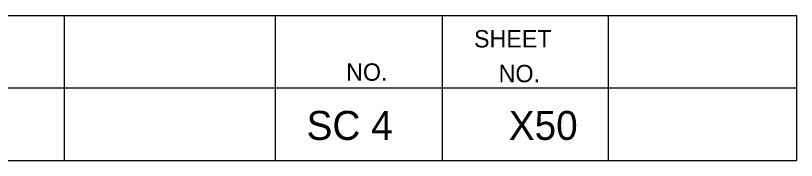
# Model space of a CAD drawing. Extents: x 1000 to 1162, y 999 to 8520.
# Drawn here: x 1148.08 to 1161.56, y 6735.05 to 6737.55 of the extents above; entities that cross this region are included whole.
import ezdxf

# ---------------------------------------------------------------- set-up
doc = ezdxf.new("R2010")
doc.units = 0
doc.layers.add('Level 20', color=7, linetype='Continuous')
doc.layers.add('Level 3', color=7, linetype='Continuous')

msp = doc.modelspace()

# ---------------------------------------------------------------- linework, layer by layer
at = {"layer": 'Level 3'}
for p, q in [((1133.055, 6737.546), (1161.555, 6737.546)), ((1133.055, 6737.546), (1161.555, 6737.546)), ((1133.055, 6737.546), (1161.555, 6737.546)), ((1133.055, 6737.546), (1161.555, 6737.546)), ((1133.055, 6737.546), (1161.555, 6737.546)), ((1133.055, 6737.546), (1161.555, 6737.546)), ((1133.055, 6737.546), (1161.555, 6737.546)), ((1133.055, 6737.546), (1161.555, 6737.546)), ((1133.055, 6737.546), (1161.555, 6737.546)), ((1133.055, 6737.546), (1161.555, 6737.546)), ((1133.055, 6737.546), (1161.555, 6737.546)), ((1133.055, 6737.546), (1161.555, 6737.546)), ((1133.055, 6737.546), (1161.555, 6737.546)), ((1133.055, 6737.546), (1161.555, 6737.546)), ((1133.055, 6737.546), (1161.555, 6737.546)), ((1133.055, 6737.546), (1161.555, 6737.546)), ((1133.055, 6737.546), (1161.555, 6737.546)), ((1133.055, 6737.546), (1161.555, 6737.546)), ((1133.055, 6737.546), (1161.555, 6737.546)), ((1133.055, 6737.546), (1161.555, 6737.546)), ((1133.055, 6737.546), (1161.555, 6737.546)), ((1133.055, 6737.546), (1161.555, 6737.546)), ((1133.055, 6737.546), (1161.555, 6737.546)), ((1133.055, 6737.546), (1161.555, 6737.546)), ((1133.055, 6737.546), (1161.555, 6737.546)), ((1133.055, 6737.546), (1161.555, 6737.546)), ((1133.055, 6737.546), (1161.555, 6737.546)), ((1133.055, 6737.546), (1161.555, 6737.546)), ((1133.055, 6737.546), (1161.555, 6737.546)), ((1133.055, 6737.546), (1161.555, 6737.546)), ((1133.055, 6737.546), (1161.555, 6737.546)), ((1133.055, 6737.546), (1161.555, 6737.546)), ((1133.055, 6737.546), (1161.555, 6737.546)), ((1133.055, 6737.546), (1161.555, 6737.546)), ((1133.055, 6737.546), (1161.555, 6737.546)), ((1133.055, 6737.546), (1161.555, 6737.546)), ((1133.055, 6737.546), (1161.555, 6737.546)), ((1133.055, 6737.546), (1161.555, 6737.546)), ((1133.055, 6737.546), (1161.555, 6737.546)), ((1133.055, 6737.546), (1161.555, 6737.546)), ((1133.055, 6737.546), (1161.555, 6737.546)), ((1133.055, 6737.546), (1161.555, 6737.546)), ((1133.055, 6737.546), (1161.555, 6737.546)), ((1133.055, 6737.546), (1161.555, 6737.546)), ((1133.055, 6737.546), (1161.555, 6737.546)), ((1133.055, 6737.546), (1161.555, 6737.546)), ((1133.055, 6737.546), (1161.555, 6737.546)), ((1133.055, 6737.546), (1161.555, 6737.546)), ((1148.913, 6737.546), (1148.913, 6735.046)), ((1148.913, 6737.546), (1148.913, 6735.046)), ((1148.913, 6737.546), (1148.913, 6735.046)), ((1148.913, 6737.546), (1148.913, 6735.046)), ((1148.913, 6737.546), (1148.913, 6735.046)), ((1148.913, 6737.546), (1148.913, 6735.046)), ((1148.913, 6737.546), (1148.913, 6735.046)), ((1148.913, 6737.546), (1148.913, 6735.046)), ((1148.913, 6737.546), (1148.913, 6735.046)), ((1148.913, 6737.546), (1148.913, 6735.046)), ((1148.913, 6737.546), (1148.913, 6735.046)), ((1148.913, 6737.546), (1148.913, 6735.046)), ((1148.913, 6737.546), (1148.913, 6735.046)), ((1148.913, 6737.546), (1148.913, 6735.046)), ((1148.913, 6737.546), (1148.913, 6735.046)), ((1148.913, 6737.546), (1148.913, 6735.046)), ((1148.913, 6737.546), (1148.913, 6735.046)), ((1148.913, 6737.546), (1148.913, 6735.046)), ((1148.913, 6737.546), (1148.913, 6735.046)), ((1148.913, 6737.546), (1148.913, 6735.046)), ((1148.913, 6737.546), (1148.913, 6735.046)), ((1148.913, 6737.546), (1148.913, 6735.046)), ((1148.913, 6737.546), (1148.913, 6735.046)), ((1148.913, 6737.546), (1148.913, 6735.046)), ((1148.913, 6737.546), (1148.913, 6735.046)), ((1148.913, 6737.546), (1148.913, 6735.046)), ((1148.913, 6737.546), (1148.913, 6735.046)), ((1148.913, 6737.546), (1148.913, 6735.046)), ((1148.913, 6737.546), (1148.913, 6735.046)), ((1148.913, 6737.546), (1148.913, 6735.046)), ((1148.913, 6737.546), (1148.913, 6735.046)), ((1148.913, 6737.546), (1148.913, 6735.046)), ((1148.913, 6737.546), (1148.913, 6735.046)), ((1148.913, 6737.546), (1148.913, 6735.046)), ((1148.913, 6737.546), (1148.913, 6735.046)), ((1148.913, 6737.546), (1148.913, 6735.046)), ((1148.913, 6737.546), (1148.913, 6735.046)), ((1148.913, 6737.546), (1148.913, 6735.046)), ((1148.913, 6737.546), (1148.913, 6735.046)), ((1148.913, 6737.546), (1148.913, 6735.046)), ((1148.913, 6737.546), (1148.913, 6735.046)), ((1148.913, 6737.546), (1148.913, 6735.046)), ((1148.913, 6737.546), (1148.913, 6735.046)), ((1148.913, 6737.546), (1148.913, 6735.046)), ((1148.913, 6737.546), (1148.913, 6735.046)), ((1148.913, 6737.546), (1148.913, 6735.046)), ((1148.913, 6737.546), (1148.913, 6735.046)), ((1148.913, 6737.546), (1148.913, 6735.046)), ((1152.554, 6737.546), (1152.554, 6735.046)), ((1152.554, 6737.546), (1152.554, 6735.046)), ((1152.554, 6737.546), (1152.554, 6735.046)), ((1152.554, 6737.546), (1152.554, 6735.046)), ((1152.554, 6737.546), (1152.554, 6735.046)), ((1152.554, 6737.546), (1152.554, 6735.046)), ((1152.554, 6737.546), (1152.554, 6735.046)), ((1152.554, 6737.546), (1152.554, 6735.046)), ((1152.554, 6737.546), (1152.554, 6735.046)), ((1152.554, 6737.546), (1152.554, 6735.046)), ((1152.554, 6737.546), (1152.554, 6735.046)), ((1152.554, 6737.546), (1152.554, 6735.046)), ((1152.554, 6737.546), (1152.554, 6735.046)), ((1152.554, 6737.546), (1152.554, 6735.046)), ((1152.554, 6737.546), (1152.554, 6735.046)), ((1152.554, 6737.546), (1152.554, 6735.046)), ((1152.554, 6737.546), (1152.554, 6735.046)), ((1152.554, 6737.546), (1152.554, 6735.046)), ((1152.554, 6737.546), (1152.554, 6735.046)), ((1152.554, 6737.546), (1152.554, 6735.046)), ((1152.554, 6737.546), (1152.554, 6735.046)), ((1152.554, 6737.546), (1152.554, 6735.046)), ((1152.554, 6737.546), (1152.554, 6735.046)), ((1152.554, 6737.546), (1152.554, 6735.046)), ((1152.554, 6737.546), (1152.554, 6735.046)), ((1152.554, 6737.546), (1152.554, 6735.046)), ((1152.554, 6737.546), (1152.554, 6735.046)), ((1152.554, 6737.546), (1152.554, 6735.046)), ((1152.554, 6737.546), (1152.554, 6735.046)), ((1152.554, 6737.546), (1152.554, 6735.046)), ((1152.554, 6737.546), (1152.554, 6735.046)), ((1152.554, 6737.546), (1152.554, 6735.046)), ((1152.554, 6737.546), (1152.554, 6735.046)), ((1152.554, 6737.546), (1152.554, 6735.046)), ((1152.554, 6737.546), (1152.554, 6735.046)), ((1152.554, 6737.546), (1152.554, 6735.046)), ((1152.554, 6737.546), (1152.554, 6735.046)), ((1152.554, 6737.546), (1152.554, 6735.046)), ((1152.554, 6737.546), (1152.554, 6735.046)), ((1152.554, 6737.546), (1152.554, 6735.046)), ((1152.554, 6737.546), (1152.554, 6735.046)), ((1152.554, 6737.546), (1152.554, 6735.046)), ((1152.554, 6737.546), (1152.554, 6735.046)), ((1152.554, 6737.546), (1152.554, 6735.046)), ((1152.554, 6737.546), (1152.554, 6735.046)), ((1152.554, 6737.546), (1152.554, 6735.046)), ((1152.554, 6737.546), (1152.554, 6735.046)), ((1152.554, 6737.546), (1152.554, 6735.046)), ((1155.44, 6737.546), (1155.44, 6735.046)), ((1155.44, 6737.546), (1155.44, 6735.046)), ((1155.44, 6737.546), (1155.44, 6735.046)), ((1155.44, 6737.546), (1155.44, 6735.046)), ((1155.44, 6737.546), (1155.44, 6735.046)), ((1155.44, 6737.546), (1155.44, 6735.046)), ((1155.44, 6737.546), (1155.44, 6735.046)), ((1155.44, 6737.546), (1155.44, 6735.046)), ((1155.44, 6737.546), (1155.44, 6735.046)), ((1155.44, 6737.546), (1155.44, 6735.046)), ((1155.44, 6737.546), (1155.44, 6735.046)), ((1155.44, 6737.546), (1155.44, 6735.046)), ((1155.44, 6737.546), (1155.44, 6735.046)), ((1155.44, 6737.546), (1155.44, 6735.046)), ((1155.44, 6737.546), (1155.44, 6735.046)), ((1155.44, 6737.546), (1155.44, 6735.046)), ((1155.44, 6737.546), (1155.44, 6735.046)), ((1155.44, 6737.546), (1155.44, 6735.046)), ((1155.44, 6737.546), (1155.44, 6735.046)), ((1155.44, 6737.546), (1155.44, 6735.046)), ((1155.44, 6737.546), (1155.44, 6735.046)), ((1155.44, 6737.546), (1155.44, 6735.046)), ((1155.44, 6737.546), (1155.44, 6735.046)), ((1155.44, 6737.546), (1155.44, 6735.046)), ((1155.44, 6737.546), (1155.44, 6735.046)), ((1155.44, 6737.546), (1155.44, 6735.046)), ((1155.44, 6737.546), (1155.44, 6735.046)), ((1155.44, 6737.546), (1155.44, 6735.046)), ((1155.44, 6737.546), (1155.44, 6735.046)), ((1155.44, 6737.546), (1155.44, 6735.046)), ((1155.44, 6737.546), (1155.44, 6735.046)), ((1155.44, 6737.546), (1155.44, 6735.046)), ((1155.44, 6737.546), (1155.44, 6735.046)), ((1155.44, 6737.546), (1155.44, 6735.046)), ((1155.44, 6737.546), (1155.44, 6735.046)), ((1155.44, 6737.546), (1155.44, 6735.046)), ((1155.44, 6737.546), (1155.44, 6735.046)), ((1155.44, 6737.546), (1155.44, 6735.046)), ((1155.44, 6737.546), (1155.44, 6735.046)), ((1155.44, 6737.546), (1155.44, 6735.046)), ((1155.44, 6737.546), (1155.44, 6735.046)), ((1155.44, 6737.546), (1155.44, 6735.046)), ((1155.44, 6737.546), (1155.44, 6735.046)), ((1155.44, 6737.546), (1155.44, 6735.046)), ((1155.44, 6737.546), (1155.44, 6735.046)), ((1155.44, 6737.546), (1155.44, 6735.046)), ((1155.44, 6737.546), (1155.44, 6735.046)), ((1155.44, 6737.546), (1155.44, 6735.046)), ((1158.305, 6737.546), (1158.305, 6735.046)), ((1158.305, 6737.546), (1158.305, 6735.046)), ((1158.305, 6737.546), (1158.305, 6735.046)), ((1158.305, 6737.546), (1158.305, 6735.046)), ((1158.305, 6737.546), (1158.305, 6735.046)), ((1158.305, 6737.546), (1158.305, 6735.046)), ((1158.305, 6737.546), (1158.305, 6735.046)), ((1158.305, 6737.546), (1158.305, 6735.046)), ((1158.305, 6737.546), (1158.305, 6735.046)), ((1158.305, 6737.546), (1158.305, 6735.046)), ((1158.305, 6737.546), (1158.305, 6735.046)), ((1158.305, 6737.546), (1158.305, 6735.046)), ((1158.305, 6737.546), (1158.305, 6735.046)), ((1158.305, 6737.546), (1158.305, 6735.046)), ((1158.305, 6737.546), (1158.305, 6735.046)), ((1158.305, 6737.546), (1158.305, 6735.046)), ((1158.305, 6737.546), (1158.305, 6735.046)), ((1158.305, 6737.546), (1158.305, 6735.046)), ((1158.305, 6737.546), (1158.305, 6735.046)), ((1158.305, 6737.546), (1158.305, 6735.046)), ((1158.305, 6737.546), (1158.305, 6735.046)), ((1158.305, 6737.546), (1158.305, 6735.046)), ((1158.305, 6737.546), (1158.305, 6735.046)), ((1158.305, 6737.546), (1158.305, 6735.046)), ((1158.305, 6737.546), (1158.305, 6735.046)), ((1158.305, 6737.546), (1158.305, 6735.046)), ((1158.305, 6737.546), (1158.305, 6735.046)), ((1158.305, 6737.546), (1158.305, 6735.046)), ((1158.305, 6737.546), (1158.305, 6735.046)), ((1158.305, 6737.546), (1158.305, 6735.046)), ((1158.305, 6737.546), (1158.305, 6735.046)), ((1158.305, 6737.546), (1158.305, 6735.046)), ((1158.305, 6737.546), (1158.305, 6735.046)), ((1158.305, 6737.546), (1158.305, 6735.046)), ((1158.305, 6737.546), (1158.305, 6735.046)), ((1158.305, 6737.546), (1158.305, 6735.046)), ((1158.305, 6737.546), (1158.305, 6735.046)), ((1158.305, 6737.546), (1158.305, 6735.046)), ((1158.305, 6737.546), (1158.305, 6735.046)), ((1158.305, 6737.546), (1158.305, 6735.046)), ((1158.305, 6737.546), (1158.305, 6735.046)), ((1158.305, 6737.546), (1158.305, 6735.046)), ((1158.305, 6737.546), (1158.305, 6735.046)), ((1158.305, 6737.546), (1158.305, 6735.046)), ((1158.305, 6737.546), (1158.305, 6735.046)), ((1158.305, 6737.546), (1158.305, 6735.046)), ((1158.305, 6737.546), (1158.305, 6735.046)), ((1158.305, 6737.546), (1158.305, 6735.046)), ((1161.555, 6737.546), (1161.555, 6735.046)), ((1161.555, 6737.546), (1161.555, 6735.046)), ((1161.555, 6737.546), (1161.555, 6735.046)), ((1161.555, 6737.546), (1161.555, 6735.046)), ((1161.555, 6737.546), (1161.555, 6735.046)), ((1161.555, 6737.546), (1161.555, 6735.046)), ((1161.555, 6737.546), (1161.555, 6735.046)), ((1161.555, 6737.546), (1161.555, 6735.046)), ((1161.555, 6737.546), (1161.555, 6735.046)), ((1161.555, 6737.546), (1161.555, 6735.046)), ((1161.555, 6737.546), (1161.555, 6735.046)), ((1161.555, 6737.546), (1161.555, 6735.046)), ((1161.555, 6737.546), (1161.555, 6735.046)), ((1161.555, 6737.546), (1161.555, 6735.046)), ((1161.555, 6737.546), (1161.555, 6735.046)), ((1161.555, 6737.546), (1161.555, 6735.046)), ((1161.555, 6737.546), (1161.555, 6735.046)), ((1161.555, 6737.546), (1161.555, 6735.046)), ((1161.555, 6737.546), (1161.555, 6735.046)), ((1161.555, 6737.546), (1161.555, 6735.046)), ((1161.555, 6737.546), (1161.555, 6735.046)), ((1161.555, 6737.546), (1161.555, 6735.046)), ((1161.555, 6737.546), (1161.555, 6735.046)), ((1161.555, 6737.546), (1161.555, 6735.046)), ((1161.555, 6737.546), (1161.555, 6735.046)), ((1161.555, 6737.546), (1161.555, 6735.046)), ((1161.555, 6737.546), (1161.555, 6735.046)), ((1161.555, 6737.546), (1161.555, 6735.046)), ((1161.555, 6737.546), (1161.555, 6735.046)), ((1161.555, 6737.546), (1161.555, 6735.046)), ((1161.555, 6737.546), (1161.555, 6735.046)), ((1161.555, 6737.546), (1161.555, 6735.046)), ((1161.555, 6737.546), (1161.555, 6735.046)), ((1161.555, 6737.546), (1161.555, 6735.046)), ((1161.555, 6737.546), (1161.555, 6735.046)), ((1161.555, 6737.546), (1161.555, 6735.046)), ((1161.555, 6737.546), (1161.555, 6735.046)), ((1161.555, 6737.546), (1161.555, 6735.046)), ((1161.555, 6737.546), (1161.555, 6735.046)), ((1161.555, 6737.546), (1161.555, 6735.046)), ((1161.555, 6737.546), (1161.555, 6735.046)), ((1161.555, 6737.546), (1161.555, 6735.046)), ((1161.555, 6737.546), (1161.555, 6735.046)), ((1161.555, 6737.546), (1161.555, 6735.046)), ((1161.555, 6737.546), (1161.555, 6735.046)), ((1161.555, 6737.546), (1161.555, 6735.046)), ((1161.555, 6737.546), (1161.555, 6735.046)), ((1161.555, 6737.546), (1161.555, 6735.046)), ((1133.055, 6736.296), (1161.555, 6736.296)), ((1133.055, 6736.296), (1161.555, 6736.296)), ((1133.055, 6736.296), (1161.555, 6736.296)), ((1133.055, 6736.296), (1161.555, 6736.296)), ((1133.055, 6736.296), (1161.555, 6736.296)), ((1133.055, 6736.296), (1161.555, 6736.296)), ((1133.055, 6736.296), (1161.555, 6736.296)), ((1133.055, 6736.296), (1161.555, 6736.296)), ((1133.055, 6736.296), (1161.555, 6736.296)), ((1133.055, 6736.296), (1161.555, 6736.296)), ((1133.055, 6736.296), (1161.555, 6736.296)), ((1133.055, 6736.296), (1161.555, 6736.296)), ((1133.055, 6736.296), (1161.555, 6736.296)), ((1133.055, 6736.296), (1161.555, 6736.296)), ((1133.055, 6736.296), (1161.555, 6736.296)), ((1133.055, 6736.296), (1161.555, 6736.296)), ((1133.055, 6736.296), (1161.555, 6736.296)), ((1133.055, 6736.296), (1161.555, 6736.296)), ((1133.055, 6736.296), (1161.555, 6736.296)), ((1133.055, 6736.296), (1161.555, 6736.296)), ((1133.055, 6736.296), (1161.555, 6736.296)), ((1133.055, 6736.296), (1161.555, 6736.296)), ((1133.055, 6736.296), (1161.555, 6736.296)), ((1133.055, 6736.296), (1161.555, 6736.296)), ((1133.055, 6736.296), (1161.555, 6736.296)), ((1133.055, 6736.296), (1161.555, 6736.296)), ((1133.055, 6736.296), (1161.555, 6736.296)), ((1133.055, 6736.296), (1161.555, 6736.296)), ((1133.055, 6736.296), (1161.555, 6736.296)), ((1133.055, 6736.296), (1161.555, 6736.296)), ((1133.055, 6736.296), (1161.555, 6736.296)), ((1133.055, 6736.296), (1161.555, 6736.296)), ((1133.055, 6736.296), (1161.555, 6736.296)), ((1133.055, 6736.296), (1161.555, 6736.296)), ((1133.055, 6736.296), (1161.555, 6736.296)), ((1133.055, 6736.296), (1161.555, 6736.296)), ((1133.055, 6736.296), (1161.555, 6736.296)), ((1133.055, 6736.296), (1161.555, 6736.296)), ((1133.055, 6736.296), (1161.555, 6736.296)), ((1133.055, 6736.296), (1161.555, 6736.296)), ((1133.055, 6736.296), (1161.555, 6736.296)), ((1133.055, 6736.296), (1161.555, 6736.296)), ((1133.055, 6736.296), (1161.555, 6736.296)), ((1133.055, 6736.296), (1161.555, 6736.296)), ((1133.055, 6736.296), (1161.555, 6736.296)), ((1133.055, 6736.296), (1161.555, 6736.296)), ((1133.055, 6736.296), (1161.555, 6736.296)), ((1133.055, 6736.296), (1161.555, 6736.296)), ((1133.055, 6735.046), (1161.555, 6735.046)), ((1133.055, 6735.046), (1161.555, 6735.046)), ((1133.055, 6735.046), (1161.555, 6735.046)), ((1133.055, 6735.046), (1161.555, 6735.046)), ((1133.055, 6735.046), (1161.555, 6735.046)), ((1133.055, 6735.046), (1161.555, 6735.046)), ((1133.055, 6735.046), (1161.555, 6735.046)), ((1133.055, 6735.046), (1161.555, 6735.046)), ((1133.055, 6735.046), (1161.555, 6735.046)), ((1133.055, 6735.046), (1161.555, 6735.046)), ((1133.055, 6735.046), (1161.555, 6735.046)), ((1133.055, 6735.046), (1161.555, 6735.046)), ((1133.055, 6735.046), (1161.555, 6735.046)), ((1133.055, 6735.046), (1161.555, 6735.046)), ((1133.055, 6735.046), (1161.555, 6735.046)), ((1133.055, 6735.046), (1161.555, 6735.046)), ((1133.055, 6735.046), (1161.555, 6735.046)), ((1133.055, 6735.046), (1161.555, 6735.046)), ((1133.055, 6735.046), (1161.555, 6735.046)), ((1133.055, 6735.046), (1161.555, 6735.046)), ((1133.055, 6735.046), (1161.555, 6735.046)), ((1133.055, 6735.046), (1161.555, 6735.046)), ((1133.055, 6735.046), (1161.555, 6735.046)), ((1133.055, 6735.046), (1161.555, 6735.046)), ((1133.055, 6735.046), (1161.555, 6735.046)), ((1133.055, 6735.046), (1161.555, 6735.046)), ((1133.055, 6735.046), (1161.555, 6735.046)), ((1133.055, 6735.046), (1161.555, 6735.046)), ((1133.055, 6735.046), (1161.555, 6735.046)), ((1133.055, 6735.046), (1161.555, 6735.046)), ((1133.055, 6735.046), (1161.555, 6735.046)), ((1133.055, 6735.046), (1161.555, 6735.046)), ((1133.055, 6735.046), (1161.555, 6735.046)), ((1133.055, 6735.046), (1161.555, 6735.046)), ((1133.055, 6735.046), (1161.555, 6735.046)), ((1133.055, 6735.046), (1161.555, 6735.046)), ((1133.055, 6735.046), (1161.555, 6735.046)), ((1133.055, 6735.046), (1161.555, 6735.046)), ((1133.055, 6735.046), (1161.555, 6735.046)), ((1133.055, 6735.046), (1161.555, 6735.046)), ((1133.055, 6735.046), (1161.555, 6735.046)), ((1133.055, 6735.046), (1161.555, 6735.046)), ((1133.055, 6735.046), (1161.555, 6735.046)), ((1133.055, 6735.046), (1161.555, 6735.046)), ((1133.055, 6735.046), (1161.555, 6735.046)), ((1133.055, 6735.046), (1161.555, 6735.046)), ((1133.055, 6735.046), (1161.555, 6735.046)), ((1133.055, 6735.046), (1161.555, 6735.046))]:
    msp.add_line(p, q, dxfattribs=at)

# ---------------------------------------------------------------- texts
at = {"layer": 'Level 20'}
for s, p in [('SC 4', (1153.099, 6735.4)), ('X50', (1156.59, 6735.4))]:
    msp.add_text(s, height=0.5, dxfattribs=at).set_placement(p)
at = {"layer": 'Level 3'}
for s, p in [('SHEET', (1155.99, 6736.996)), ('SHEET', (1155.99, 6736.996)), ('SHEET', (1155.99, 6736.996)), ('SHEET', (1155.99, 6736.996)), ('SHEET', (1155.99, 6736.996)), ('SHEET', (1155.99, 6736.996)), ('SHEET', (1155.99, 6736.996)), ('SHEET', (1155.99, 6736.996)), ('SHEET', (1155.99, 6736.996)), ('SHEET', (1155.99, 6736.996)), ('SHEET', (1155.99, 6736.996)), ('SHEET', (1155.99, 6736.996)), ('SHEET', (1155.99, 6736.996)), ('SHEET', (1155.99, 6736.996)), ('SHEET', (1155.99, 6736.996)), ('SHEET', (1155.99, 6736.996)), ('SHEET', (1155.99, 6736.996)), ('SHEET', (1155.99, 6736.996)), ('SHEET', (1155.99, 6736.996)), ('SHEET', (1155.99, 6736.996)), ('SHEET', (1155.99, 6736.996)), ('SHEET', (1155.99, 6736.996)), ('SHEET', (1155.99, 6736.996)), ('SHEET', (1155.99, 6736.996)), ('SHEET', (1155.99, 6736.996)), ('SHEET', (1155.99, 6736.996)), ('SHEET', (1155.99, 6736.996)), ('SHEET', (1155.99, 6736.996)), ('SHEET', (1155.99, 6736.996)), ('SHEET', (1155.99, 6736.996)), ('SHEET', (1155.99, 6736.996)), ('SHEET', (1155.99, 6736.996)), ('SHEET', (1155.99, 6736.996)), ('SHEET', (1155.99, 6736.996)), ('SHEET', (1155.99, 6736.996)), ('SHEET', (1155.99, 6736.996)), ('SHEET', (1155.99, 6736.996)), ('SHEET', (1155.99, 6736.996)), ('SHEET', (1155.99, 6736.996)), ('SHEET', (1155.99, 6736.996)), ('SHEET', (1155.99, 6736.996)), ('SHEET', (1155.99, 6736.996)), ('SHEET', (1155.99, 6736.996)), ('SHEET', (1155.99, 6736.996)), ('SHEET', (1155.99, 6736.996)), ('SHEET', (1155.99, 6736.996)), ('SHEET', (1155.99, 6736.996)), ('SHEET', (1155.99, 6736.996)), ('NO.', (1153.782, 6736.421)), ('NO.', (1153.782, 6736.421)), ('NO.', (1153.782, 6736.421)), ('NO.', (1153.782, 6736.421)), ('NO.', (1153.782, 6736.421)), ('NO.', (1153.782, 6736.421)), ('NO.', (1153.782, 6736.421)), ('NO.', (1153.782, 6736.421)), ('NO.', (1153.782, 6736.421)), ('NO.', (1153.782, 6736.421)), ('NO.', (1153.782, 6736.421)), ('NO.', (1153.782, 6736.421)), ('NO.', (1153.782, 6736.421)), ('NO.', (1153.782, 6736.421)), ('NO.', (1153.782, 6736.421)), ('NO.', (1153.782, 6736.421)), ('NO.', (1153.782, 6736.421)), ('NO.', (1153.782, 6736.421)), ('NO.', (1153.782, 6736.421)), ('NO.', (1153.782, 6736.421)), ('NO.', (1153.782, 6736.421)), ('NO.', (1153.782, 6736.421)), ('NO.', (1153.782, 6736.421)), ('NO.', (1153.782, 6736.421)), ('NO.', (1153.782, 6736.421)), ('NO.', (1153.782, 6736.421)), ('NO.', (1153.782, 6736.421)), ('NO.', (1153.782, 6736.421)), ('NO.', (1153.782, 6736.421)), ('NO.', (1153.782, 6736.421)), ('NO.', (1153.782, 6736.421)), ('NO.', (1153.782, 6736.421)), ('NO.', (1153.782, 6736.421)), ('NO.', (1153.782, 6736.421)), ('NO.', (1153.782, 6736.421)), ('NO.', (1153.782, 6736.421)), ('NO.', (1153.782, 6736.421)), ('NO.', (1153.782, 6736.421)), ('NO.', (1153.782, 6736.421)), ('NO.', (1153.782, 6736.421)), ('NO.', (1153.782, 6736.421)), ('NO.', (1153.782, 6736.421)), ('NO.', (1153.782, 6736.421)), ('NO.', (1153.782, 6736.421)), ('NO.', (1153.782, 6736.421)), ('NO.', (1153.782, 6736.421)), ('NO.', (1153.782, 6736.421)), ('NO.', (1153.782, 6736.421)), ('NO.', (1156.415, 6736.396)), ('NO.', (1156.415, 6736.396)), ('NO.', (1156.415, 6736.396)), ('NO.', (1156.415, 6736.396)), ('NO.', (1156.415, 6736.396)), ('NO.', (1156.415, 6736.396)), ('NO.', (1156.415, 6736.396)), ('NO.', (1156.415, 6736.396)), ('NO.', (1156.415, 6736.396)), ('NO.', (1156.415, 6736.396)), ('NO.', (1156.415, 6736.396)), ('NO.', (1156.415, 6736.396)), ('NO.', (1156.415, 6736.396)), ('NO.', (1156.415, 6736.396)), ('NO.', (1156.415, 6736.396)), ('NO.', (1156.415, 6736.396)), ('NO.', (1156.415, 6736.396)), ('NO.', (1156.415, 6736.396)), ('NO.', (1156.415, 6736.396)), ('NO.', (1156.415, 6736.396)), ('NO.', (1156.415, 6736.396)), ('NO.', (1156.415, 6736.396)), ('NO.', (1156.415, 6736.396)), ('NO.', (1156.415, 6736.396)), ('NO.', (1156.415, 6736.396)), ('NO.', (1156.415, 6736.396)), ('NO.', (1156.415, 6736.396)), ('NO.', (1156.415, 6736.396)), ('NO.', (1156.415, 6736.396)), ('NO.', (1156.415, 6736.396)), ('NO.', (1156.415, 6736.396)), ('NO.', (1156.415, 6736.396)), ('NO.', (1156.415, 6736.396)), ('NO.', (1156.415, 6736.396)), ('NO.', (1156.415, 6736.396)), ('NO.', (1156.415, 6736.396)), ('NO.', (1156.415, 6736.396)), ('NO.', (1156.415, 6736.396)), ('NO.', (1156.415, 6736.396)), ('NO.', (1156.415, 6736.396)), ('NO.', (1156.415, 6736.396)), ('NO.', (1156.415, 6736.396)), ('NO.', (1156.415, 6736.396)), ('NO.', (1156.415, 6736.396)), ('NO.', (1156.415, 6736.396)), ('NO.', (1156.415, 6736.396)), ('NO.', (1156.415, 6736.396)), ('NO.', (1156.415, 6736.396))]:
    msp.add_text(s, height=0.3, dxfattribs=at).set_placement(p)

doc.saveas('drawing.dxf')
